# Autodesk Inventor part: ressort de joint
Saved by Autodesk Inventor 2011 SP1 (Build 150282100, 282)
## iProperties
Created: 2010-12
Part Number: ressort de joint
Document SubType Name: Modeling
Designer: eric
Density: 1 g/cm^3
Author: eric
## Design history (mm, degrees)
feature "Base1"
node "Solide1"
node "Corps solides"
node "Corps surfaciques"
